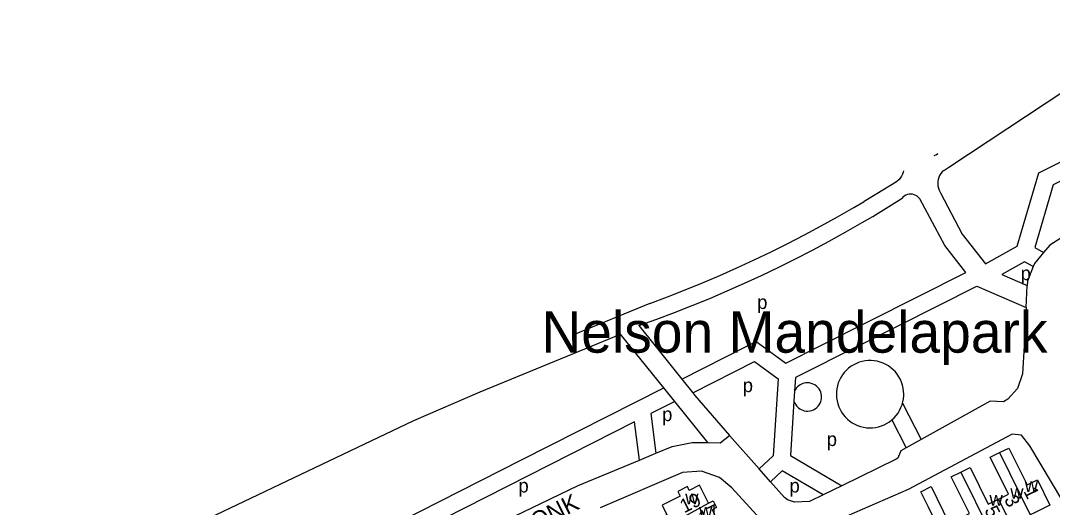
# Model space of a CAD drawing. Extents: x 157794 to 159375, y 380877 to 382306.
# Drawn here: x 158274.4 to 158574.4, y 381703 to 381844.5 of the extents above; entities that cross this region are included whole.
import ezdxf

# ---------------------------------------------------------------- set-up
doc = ezdxf.new("R2010")
doc.units = 0
for name, color, linetype in [('BLT_Basislijn', 7, 'Continuous'), ('BLT_Bebouwing', 7, 'Continuous'), ('BLT_Centroide', 7, 'Continuous'), ('BLT_Huisnummer', 7, 'Continuous'), ('BLT_Huisnummer_ tussenligend', 7, 'Continuous'), ('BLT_Onderverdeling_panden', 7, 'Continuous'), ('BLT_Sport_parknaam', 7, 'Continuous'), ('BLT_Straatnaam', 7, 'Continuous')]:
    doc.layers.add(name, color=color, linetype=linetype)

msp = doc.modelspace()

# ---------------------------------------------------------------- linework, layer by layer
at = {"layer": 'BLT_Basislijn'}
for p, q in [((158544.32, 381801.91), (158578.38, 381824.43)), ((158542.82, 381801.02), (158544.32, 381801.91)), ((158522.21, 381787.64), (158530.75, 381792.97)), ((158566.77, 381761.16), (158567.1, 381767.56)), ((158457.38, 381762.33), (158435.14, 381753.16)), ((158566.77, 381761.16), (158566.21, 381750)), ((158454.21, 381755.87), (158458.89, 381750)), ((158440.59, 381750), (158448.83, 381753.4)), ((158451.58, 381750), (158448.83, 381753.4)), ((158408.05, 381736.58), (158440.59, 381750)), ((158461.4, 381737.82), (158451.58, 381750)), ((158458.89, 381750), (158466.65, 381740.27)), ((158466.65, 381740.27), (158485.8, 381750)), ((158466.65, 381740.27), (158469.83, 381736.28)), ((158464.61, 381733.84), (158461.4, 381737.82)), ((158474.25, 381721.91), (158464.61, 381733.84)), ((158530.83, 381733.29), (158536.32, 381722.75)), ((158527.72, 381728.44), (158531.95, 381720.32)), ((158489.11, 381714.18), (158480.5, 381723.89)), ((158536.32, 381722.75), (158531.95, 381720.32)), ((158454.33, 381716.79), (158459.12, 381718.78)), ((158492.43, 381710.44), (158489.11, 381714.18)), ((158513.16, 381709.31), (158507.77, 381706.68))]:
    msp.add_line(p, q, dxfattribs=at)
for points in [[(158541.88, 381794.51), (158548.15, 381782.45), (158554.97, 381773.8), (158564.21, 381779), (158570.52, 381800.26), (158615.96, 381822.99), (158618.82, 381844.55)], [(158628.18, 381811.05), (158618.03, 381818.43), (158574.7, 381796.76), (158569.29, 381778.54), (158571.89, 381777.11)], [(158628.18, 381811.05), (158618.42, 381805.59), (158616.48, 381806.03), (158615.15, 381805.61), (158604.46, 381798.88), (158603.74, 381798.69), (158601.57, 381796.99), (158573.68, 381779.26), (158571.89, 381777.11)], [(158540.1, 381805.38), (158540.5, 381805.53), (158541.06, 381805.84), (158541.18, 381805.92)], [(158531.13, 381800.91), (158531.04, 381800.49), (158530.83, 381799.89), (158530.55, 381799.32), (158530.2, 381798.78), (158529.79, 381798.3), (158529.31, 381797.87), (158529.1, 381797.7)], [(158542.82, 381801.02), (158542.37, 381800.58), (158541.98, 381800.08), (158541.65, 381799.54), (158541.39, 381798.97), (158541.21, 381798.36), (158541.1, 381797.74), (158541.08, 381797.11), (158541.13, 381796.48), (158541.27, 381795.86), (158541.48, 381795.26), (158541.76, 381794.7), (158541.88, 381794.51)], [(158529.1, 381797.7), (158523.42, 381794.15), (158519.66, 381791.94)], [(158535.84, 381792.73), (158535.52, 381793.13), (158535.15, 381793.47), (158534.73, 381793.74), (158534.26, 381793.94), (158533.78, 381794.07), (158533.27, 381794.12), (158532.77, 381794.09), (158532.28, 381793.98), (158531.81, 381793.8), (158531.37, 381793.54), (158530.98, 381793.22), (158530.75, 381792.97)], [(158457.38, 381762.33), (158462.5, 381764.25), (158467.6, 381766.24), (158472.66, 381768.32), (158477.69, 381770.46), (158482.7, 381772.68), (158487.67, 381774.97), (158492.6, 381777.33), (158497.5, 381779.77), (158502.37, 381782.27), (158507.19, 381784.85), (158511.98, 381787.5), (158516.73, 381790.22), (158519.66, 381791.94)], [(158506.89, 381750), (158549.27, 381771.33), (158543.13, 381779.13), (158535.84, 381792.73)], [(158454.21, 381755.87), (158459.39, 381757.74), (158464.55, 381759.68), (158469.67, 381761.69), (158474.77, 381763.78), (158479.84, 381765.94), (158484.87, 381768.17), (158489.88, 381770.48), (158494.84, 381772.86), (158499.77, 381775.31), (158504.67, 381777.84), (158509.53, 381780.43), (158514.35, 381783.1), (158519.13, 381785.83), (158522.21, 381787.64)], [(158571.89, 381777.11), (158569.23, 381773.91), (158568.88, 381773.05)], [(158568.88, 381773.05), (158566.33, 381774.46), (158559.75, 381770.75), (158567.1, 381767.56)], [(158568.88, 381773.05), (158567.16, 381768.82), (158567.1, 381767.56)], [(158518.01, 381750), (158552.49, 381767.36), (158566.77, 381761.16)], [(158485.8, 381750), (158488.31, 381751.27), (158490.05, 381750)], [(158490.05, 381750), (158496.91, 381744.98), (158506.89, 381750)], [(158518.01, 381750), (158499.7, 381740.78), (158499.44, 381736.79)], [(158566.21, 381750), (158565.79, 381741.84), (158564.3, 381737.61), (158561.43, 381734.52), (158560.23, 381733.73), (158556.34, 381733.88), (158536.32, 381722.75)], [(158469.83, 381736.28), (158487.83, 381745.43), (158494.66, 381740.43), (158493.25, 381718.05), (158489.11, 381714.18)], [(158531.21, 381735.93), (158531.17, 381736.82), (158531.05, 381737.7), (158530.85, 381738.56), (158530.58, 381739.4), (158530.23, 381740.21), (158529.8, 381740.99), (158529.31, 381741.73), (158528.76, 381742.42), (158528.14, 381743.06), (158527.47, 381743.64), (158526.75, 381744.15), (158525.99, 381744.6), (158525.19, 381744.98), (158524.36, 381745.28), (158523.5, 381745.51), (158522.63, 381745.66), (158521.75, 381745.73), (158520.86, 381745.72), (158519.98, 381745.63), (158519.11, 381745.47), (158518.26, 381745.22), (158517.44, 381744.9), (158516.65, 381744.51), (158515.89, 381744.04), (158515.18, 381743.51), (158514.52, 381742.92), (158513.92, 381742.27), (158513.38, 381741.57), (158512.9, 381740.82), (158512.5, 381740.03), (158512.17, 381739.21), (158511.91, 381738.37), (158511.73, 381737.5), (158511.62, 381736.62), (158511.6, 381735.74), (158511.66, 381734.85), (158511.8, 381733.98), (158512.01, 381733.12), (158512.31, 381732.28), (158512.67, 381731.48), (158513.11, 381730.71), (158513.62, 381729.98), (158514.18, 381729.3), (158514.81, 381728.68), (158515.49, 381728.11), (158516.22, 381727.61), (158517, 381727.18), (158517.8, 381726.82), (158518.64, 381726.53), (158519.5, 381726.32), (158520.38, 381726.18), (158521.26, 381726.13), (158522.15, 381726.16), (158523.02, 381726.26), (158523.89, 381726.45), (158524.74, 381726.71), (158525.55, 381727.05), (158526.34, 381727.46), (158527.08, 381727.94), (158527.72, 381728.44)], [(158420.02, 381716.83), (158461.4, 381737.82)], [(158507.27, 381734.64), (158507.3, 381735.08), (158507.28, 381735.54), (158507.2, 381736.02), (158507.06, 381736.51), (158506.85, 381737), (158506.56, 381737.47), (158506.21, 381737.91), (158505.8, 381738.3), (158505.34, 381738.63), (158504.84, 381738.89), (158504.32, 381739.08), (158503.79, 381739.19), (158503.27, 381739.23), (158502.76, 381739.21), (158502.29, 381739.13), (158501.85, 381739.01), (158501.45, 381738.84), (158501.05, 381738.63), (158500.67, 381738.36), (158500.29, 381738.04), (158499.95, 381737.65), (158499.65, 381737.2), (158499.44, 381736.79)], [(158304.48, 381688.15), (158388.7, 381728.32), (158408.05, 381736.58)], [(158469.83, 381736.28), (158470.41, 381735.55), (158480.5, 381723.89)], [(158499.44, 381736.79), (158499.26, 381733.95)], [(158499.26, 381733.95), (158499.45, 381733.45), (158499.69, 381732.99), (158499.97, 381732.59), (158500.28, 381732.23), (158500.62, 381731.93), (158500.97, 381731.68), (158501.36, 381731.45), (158501.81, 381731.27), (158502.29, 381731.12), (158502.81, 381731.04), (158503.35, 381731.03), (158503.9, 381731.09), (158504.45, 381731.22), (158504.98, 381731.43), (158505.47, 381731.71), (158505.91, 381732.05), (158506.3, 381732.44), (158506.62, 381732.87), (158506.87, 381733.31), (158507.06, 381733.76), (158507.19, 381734.21), (158507.27, 381734.64)], [(158530.83, 381733.29), (158530.95, 381733.69), (158531.11, 381734.56), (158531.2, 381735.45), (158531.21, 381735.93)], [(158464.61, 381733.84), (158457.64, 381730.3), (158459.12, 381718.78)], [(158499.26, 381733.95), (158498.26, 381718.08), (158513.16, 381709.31)], [(158527.72, 381728.44), (158528.43, 381729.09), (158529.02, 381729.75), (158529.54, 381730.46), (158530, 381731.22), (158530.39, 381732.02), (158530.71, 381732.84), (158530.83, 381733.29)], [(158454.33, 381716.79), (158452.9, 381727.9), (158378.79, 381690.29), (158374.31, 381692.29), (158357.67, 381684.05), (158356.35, 381669.32)], [(158474.25, 381721.91), (158477.81, 381721.77), (158480.5, 381723.89)], [(158580.51, 381699.78), (158567.92, 381720.9), (158565.41, 381723.98), (158562.71, 381724.29), (158532.48, 381708.17), (158505.69, 381696.56)], [(158459.12, 381718.78), (158463.88, 381720.76), (158469.69, 381721.88), (158474.25, 381721.91)], [(158531.95, 381720.32), (158530.39, 381719.46), (158529.46, 381717.34), (158528.98, 381717.02), (158513.16, 381709.31)], [(158274.37, 381644.79), (158283.68, 381649.22), (158284.28, 381653.34), (158374.19, 381697.81), (158378.65, 381695.83), (158420.02, 381716.83)], [(158364.84, 381672.97), (158371.57, 381677.18), (158372.03, 381679.06), (158372.58, 381679.79), (158401.25, 381694.41), (158404.72, 381694.11), (158436.48, 381709.38), (158454.33, 381716.79)], [(158495.94, 381691.95), (158495.56, 381692.97), (158481.18, 381708.68), (158477.65, 381711.69), (158472.34, 381713.52), (158466.83, 381713.16), (158442.96, 381702.88)], [(158507.77, 381706.68), (158495.89, 381713.68), (158492.43, 381710.44)], [(158507.77, 381706.68), (158503.84, 381704.77), (158499.39, 381704.5), (158497.38, 381705.21), (158496.51, 381705.85), (158492.43, 381710.44)]]:
    msp.add_lwpolyline(points, dxfattribs=at)
at = {"layer": 'BLT_Bebouwing'}
for points in [[(158559.08, 381718.93), (158561.79, 381720.26), (158567.07, 381709.57), (158570.06, 381711.05), (158573.69, 381703.7), (158569.21, 381701.48), (158567.99, 381700.88)], [(158558.74, 381705.4), (158561.68, 381706.85), (158556.38, 381717.59), (158559.08, 381718.93)], [(158547.38, 381699.8), (158550.32, 381701.25), (158545.04, 381711.94), (158547.78, 381713.29)], [(158547.78, 381713.29), (158550.51, 381714.64), (158555.8, 381703.94), (158558.74, 381705.4)], [(158474.4, 381704.24), (158471.82, 381709.43), (158468.84, 381707.95), (158468.28, 381709.06), (158465.51, 381707.68), (158466.2, 381706.29), (158460.92, 381703.67), (158462.33, 381700.84), (158459.78, 381699.57), (158460.98, 381697.16), (158463.53, 381698.43), (158466.52, 381699.91)], [(158550.99, 381692.49), (158545.06, 381689.56), (158538.38, 381703.08), (158536.16, 381707.57), (158539.17, 381709.05), (158544.45, 381698.36), (158547.38, 381699.8)], [(158474.4, 381704.24), (158475.75, 381704.91), (158476.73, 381702.94), (158475.49, 381702.32), (158477.03, 381699.22)]]:
    msp.add_lwpolyline(points, dxfattribs=at)
at = {"layer": 'BLT_Onderverdeling_panden'}
for p, q in [((158559.08, 381718.93), (158567.99, 381700.88)), ((158547.78, 381713.29), (158556.67, 381695.29)), ((158466.52, 381699.91), (158474.4, 381704.24)), ((158558.74, 381705.4), (158562.34, 381698.09))]:
    msp.add_line(p, q, dxfattribs=at)

# ---------------------------------------------------------------- texts
at = {"layer": 'BLT_Centroide'}
for s, p in [('p', (158565.21, 381769.1)), ('p', (158488.58, 381760.7)), ('p', (158484.39, 381736.53)), ('p', (158460.94, 381728.11)), ('p', (158508.82, 381720.85)), ('p', (158419.15, 381707.35)), ('p', (158497.98, 381707.35)), ('w', (158566.39, 381707.53)), ('w', (158562.19, 381705.53)), ('w', (158467.65, 381703.94)), ('w', (158556.14, 381703.5)), ('w', (158471.68, 381700.03))]:
    msp.add_text(s, height=4, dxfattribs=at).set_placement(p)
at = {"layer": 'BLT_Huisnummer'}
for s, rotation, p in [('19', 26.4619, (158467.35, 381701.26)), ('1', 296.2824, (158565.95, 381707.75)), ('5', 296.2824, (158554.59, 381702.29))]:
    msp.add_text(s, height=4, rotation=rotation, dxfattribs=at).set_placement(p)
at = {"layer": 'BLT_Huisnummer_ tussenligend'}
for s, rotation, p in [('3', 296.2824, (158560.33, 381705.36)), ('17', 26.4619, (158472.78, 381697.89))]:
    msp.add_text(s, height=4, rotation=rotation, dxfattribs=at).set_placement(p)
at = {"layer": 'BLT_Sport_parknaam'}
msp.add_text('Nelson Mandelapark', height=12, dxfattribs=at).set_placement((158425.83, 381748))
at = {"layer": 'BLT_Straatnaam'}
msp.add_text('RAVENSDONK', height=5, rotation=26.261, dxfattribs=at).set_placement((158395.27, 381682.03))

doc.saveas('drawing.dxf')
